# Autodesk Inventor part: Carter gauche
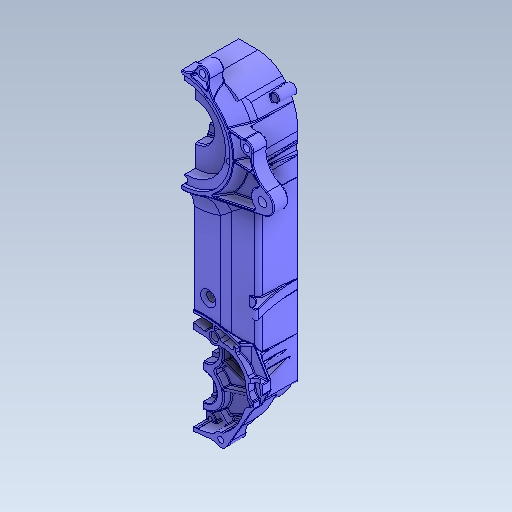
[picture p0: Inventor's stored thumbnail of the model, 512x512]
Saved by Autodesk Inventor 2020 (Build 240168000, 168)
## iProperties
Created: 2003-05
Part Number: Carter gauche
Material: Générique
Document SubType Name: Modeling
Designer: Bruno
Density: 1 g/cm^3
Appearance: Par défaut
Author: Bruno
Sending System: SolidWorks 2011
Last Author: Professeur
Last Saved: 2014-11-07
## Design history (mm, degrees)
feature "COUPE"
node "Solide1"
